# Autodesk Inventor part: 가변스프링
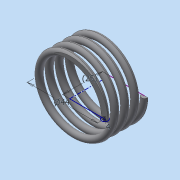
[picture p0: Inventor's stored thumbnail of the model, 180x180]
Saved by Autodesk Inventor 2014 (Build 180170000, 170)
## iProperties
Created: 2023-07
Part Number: 가변스프링
Material: 일반
Document SubType Name: Modeling
Designer: dg
Density: 1 g/cm^3
Appearance: 기본값
Author: dg
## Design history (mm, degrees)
sketch "스케치1"
  geometry: L1 (22, 0)-(0, 0); L2 (0, 0)-(0, 25); L3 (0, 25)-(22, 25); C1 r 2 at (22, 0)
  constraints: 6 end point, 2 parallel, 1 centre point, 1 coincident, 1 horizontal, 1 perpendicular
  dimensions: "d0" = 25 distance of L1.end L2.end (derived); "d1" = 4 diameter of C1; "d2" = 44 diameter of L1.start L2
feature "코일1" pitch "d3" = 10; turns "d5" = 4; dims "d4" = 25 (= d0), "d6" = 0, angle "d7" = 90 deg, angle "d8" = 90 deg, "d9" = 0, "d10" = 0
node "작업 평면1"
node "작업 평면2"
feature "분할1"
feature "분할2"
node "솔리드1"
other parameters: "d11" = 0, "d12" = 90 deg
